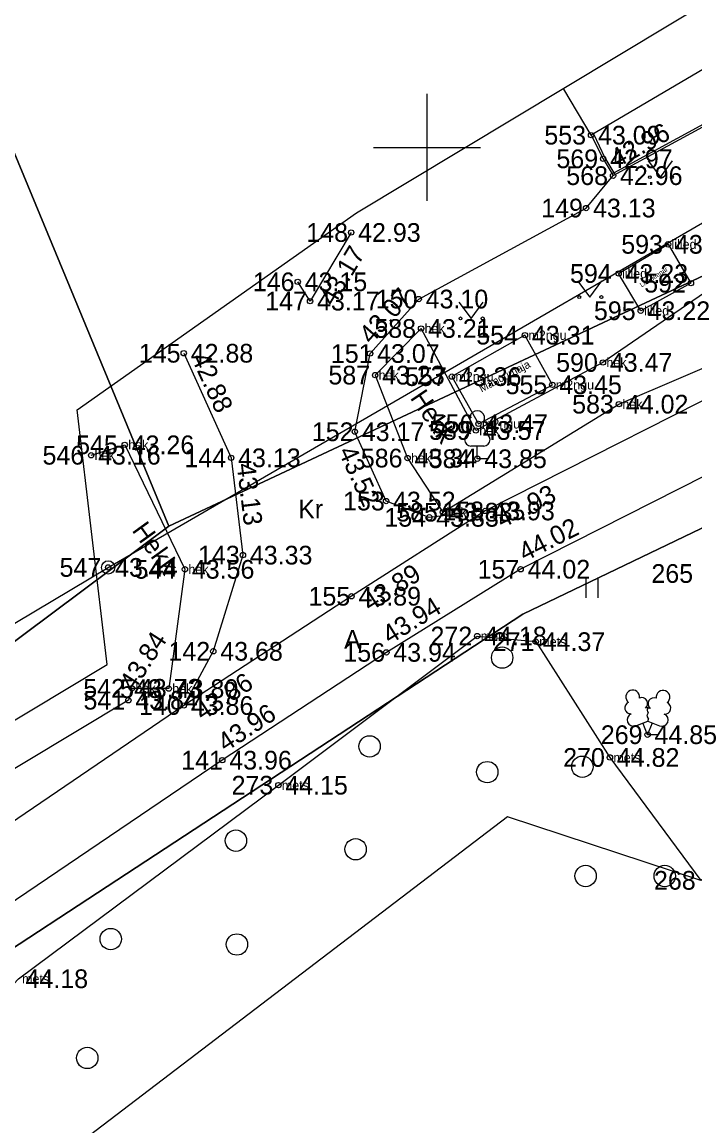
# Model space of a CAD drawing. Extents: x 505800 to 507326, y 6540058 to 6542128.
# Drawn here: x 506334.84 to 506360.03, y 6540313.38 to 6540354.69 of the extents above; entities that cross this region are included whole.
import ezdxf

# ---------------------------------------------------------------- set-up
doc = ezdxf.new("R2010")
doc.units = 0
for name, color, linetype in [('AED', 7, 'Continuous'), ('HALJASTUS', 7, 'Continuous'), ('HOONE', 7, 'Continuous'), ('KORGUS-EH2000', 7, 'Continuous'), ('MAAMUDEL', 7, 'Continuous'), ('MOOTKORG-EH2000', 7, 'Continuous'), ('MOOTMPUNKT', 7, 'Continuous'), ('MOOTNR', 7, 'Continuous'), ('MOOTPIIR', 7, 'Continuous'), ('MPOHULIIN', 7, 'Continuous'), ('PIIR', 7, 'Continuous'), ('POST', 7, 'Continuous'), ('PUU', 7, 'Continuous'), ('TEE', 7, 'Continuous'), ('VORK', 7, 'Continuous')]:
    doc.layers.add(name, color=color, linetype=linetype)

msp = doc.modelspace()

# ---------------------------------------------------------------- linework, layer by layer
at = {"layer": 'AED'}
msp.add_lwpolyline([(506338.82, 6540329.309), (506330.987, 6540324.61), (506320.117, 6540318.11)], dxfattribs=at)
at = {"layer": 'HALJASTUS'}
for p, q in [((506358.279, 6540349.492), (506358.742, 6540348.886)), ((506358.742, 6540348.886), (506359.188, 6540349.492)), ((506355.636, 6540345.005), (506356.1, 6540344.399)), ((506356.1, 6540344.399), (506356.545, 6540345.005)), ((506351.192, 6540344.204), (506351.656, 6540343.598)), ((506351.656, 6540343.598), (506352.101, 6540344.204)), ((506355.943, 6540333.904), (506355.943, 6540333.143)), ((506356.398, 6540333.904), (506356.398, 6540333.143))]:
    msp.add_line(p, q, dxfattribs=at)
for points in [[(506366.11, 6540347.866), (506361.968, 6540345.638), (506356.585, 6540341.95), (506351.827, 6540339.404), (506349.779, 6540343.223), (506348.059, 6540341.477), (506349.272, 6540338.372), (506350.597, 6540336.346), (506357.184, 6540340.389), (506361.938, 6540342.428), (506367.253, 6540345.293), (506366.11, 6540347.866)], [(506359.881, 6540344.919), (506357.999, 6540343.887), (506357.173, 6540345.28), (506359.023, 6540346.372), (506359.881, 6540344.919)], [(506337.427, 6540338.478), (506338.685, 6540338.868), (506340.937, 6540334.208), (506340.332, 6540329.743), (506338.953, 6540329.754), (506338.82, 6540329.309)], [(506306.227, 6540291.97), (506307.537, 6540296.92), (506309.208, 6540301.088), (506313.28, 6540303.838), (506321.716, 6540309.454), (506329.329, 6540313.144), (506334.711, 6540318.885), (506344.435, 6540326.129), (506351.88, 6540331.712), (506354.071, 6540331.501), (506356.847, 6540327.167), (506360.247, 6540322.568)]]:
    msp.add_lwpolyline(points, dxfattribs=at)
for centre, radius in [((506358.341, 6540348.886), 0.055), ((506359.17, 6540348.886), 0.055), ((506355.699, 6540344.399), 0.055), ((506356.527, 6540344.399), 0.055), ((506351.254, 6540343.598), 0.055), ((506352.083, 6540343.598), 0.055), ((506352.814, 6540330.904), 0.4), ((506347.85, 6540327.579), 0.4), ((506355.817, 6540326.818), 0.4), ((506352.254, 6540326.617), 0.4), ((506342.845, 6540324.053), 0.4), ((506347.329, 6540323.733), 0.4), ((506355.937, 6540322.731), 0.4), ((506358.9, 6540322.731), 0.4), ((506338.161, 6540320.368), 0.4), ((506342.885, 6540320.167), 0.4), ((506337.28, 6540315.921), 0.4)]:
    msp.add_circle(centre, radius, dxfattribs=at)
at = {"layer": 'HOONE'}
for p, q in [((506362.205, 6540354.024), (506356.142, 6540350.457)), ((506356.142, 6540350.457), (506355.128, 6540352.181))]:
    msp.add_line(p, q, dxfattribs=at)
msp.add_lwpolyline([(506350.932, 6540341.421), (506351.927, 6540339.655), (506354.692, 6540341.114), (506353.665, 6540342.972), (506350.932, 6540341.421)], dxfattribs=at)
at = {"layer": 'KORGUS-EH2000'}
for centre in [(506356.142, 6540350.457), (506356.594, 6540349.573), (506356.964, 6540348.942), (506355.956, 6540347.73), (506347.161, 6540346.815), (506359.023, 6540346.372), (506357.173, 6540345.28), (506345.16, 6540344.968), (506359.881, 6540344.919), (506345.623, 6540344.246), (506349.689, 6540344.324), (506357.999, 6540343.887), (506349.779, 6540343.223), (506353.665, 6540342.972), (506340.893, 6540342.297), (506347.871, 6540342.285), (506356.585, 6540341.95), (506348.059, 6540341.477), (506350.932, 6540341.421), (506354.692, 6540341.114), (506357.184, 6540340.389), (506351.827, 6540339.404), (506351.927, 6540339.655), (506347.299, 6540339.357), (506338.685, 6540338.868), (506337.427, 6540338.478), (506342.668, 6540338.381), (506349.272, 6540338.372), (506351.884, 6540338.347), (506348.468, 6540336.763), (506350.086, 6540336.154), (506350.597, 6540336.346), (506352.182, 6540336.393), (506343.108, 6540334.74), (506338.064, 6540334.279), (506340.937, 6540334.208), (506353.506, 6540334.212), (506347.174, 6540333.201), (506351.88, 6540331.712), (506342.001, 6540331.14), (506354.071, 6540331.501), (506348.479, 6540331.101), (506338.953, 6540329.754), (506340.332, 6540329.743), (506338.82, 6540329.309), (506340.898, 6540329.111), (506358.257, 6540328.019), (506342.338, 6540327.065), (506356.847, 6540327.167), (506344.435, 6540326.129)]:
    msp.add_circle(centre, 0.1, dxfattribs=at)
at = {"layer": 'MOOTMPUNKT'}
for centre in [(506356.142, 6540350.457), (506356.594, 6540349.573), (506356.964, 6540348.942), (506355.956, 6540347.73), (506347.161, 6540346.815), (506359.023, 6540346.372), (506357.173, 6540345.28), (506345.16, 6540344.968), (506359.881, 6540344.919), (506345.623, 6540344.246), (506349.689, 6540344.324), (506357.999, 6540343.887), (506349.779, 6540343.223), (506353.665, 6540342.972), (506340.893, 6540342.297), (506347.871, 6540342.285), (506356.585, 6540341.95), (506348.059, 6540341.477), (506350.932, 6540341.421), (506354.692, 6540341.114), (506357.184, 6540340.389), (506351.827, 6540339.404), (506351.927, 6540339.655), (506347.299, 6540339.357), (506338.685, 6540338.868), (506337.427, 6540338.478), (506342.668, 6540338.381), (506349.272, 6540338.372), (506351.884, 6540338.347), (506348.468, 6540336.763), (506350.086, 6540336.154), (506350.597, 6540336.346), (506352.182, 6540336.393), (506343.108, 6540334.74), (506338.064, 6540334.279), (506340.937, 6540334.208), (506353.506, 6540334.212), (506347.174, 6540333.201), (506351.88, 6540331.712), (506342.001, 6540331.14), (506354.071, 6540331.501), (506348.479, 6540331.101), (506338.953, 6540329.754), (506340.332, 6540329.743), (506338.82, 6540329.309), (506340.898, 6540329.111), (506358.257, 6540328.019), (506342.338, 6540327.065), (506356.847, 6540327.167), (506344.435, 6540326.129)]:
    msp.add_circle(centre, 0.1, dxfattribs=at)
at = {"layer": 'MOOTPIIR'}
for points in [[(506240.253, 6540270.959), (506245.955, 6540263.864), (506266.133, 6540270.794), (506275.983, 6540276.683), (506285.511, 6540285.657), (506298.843, 6540299.878), (506301.086, 6540304.525), (506297.722, 6540312.738), (506305.023, 6540318.445), (506309.38, 6540311.746), (506312.325, 6540315.185), (506338.029, 6540330.648), (506336.908, 6540340.183), (506347.357, 6540347.554), (506370.89, 6540361.705), (506382.389, 6540366.462), (506390.076, 6540368.866), (506400.572, 6540374.13), (506410.565, 6540381.71), (506441.143, 6540393.151), (506453.59, 6540403.335), (506461.402, 6540393.473), (506495.448, 6540402.285)], [(506495.183, 6540386.603), (506455.807, 6540378.751), (506413.936, 6540356.957), (506411.426, 6540354.112), (506402.307, 6540351.523), (506391.999, 6540341.498), (506380.901, 6540334.942), (506360.247, 6540322.568), (506353.013, 6540324.95), (506332.133, 6540309.036), (506315.598, 6540297.889), (506301.375, 6540281.904), (506292.827, 6540267.673), (506286.653, 6540264.508), (506248.469, 6540250.071)]]:
    msp.add_lwpolyline(points, dxfattribs=at)
at = {"layer": 'MPOHULIIN'}
msp.add_line((506305.802, 6540315.044), (506338.064, 6540334.279), dxfattribs=at)
msp.add_lwpolyline([(506338.064, 6540334.279), (506372.493, 6540354.233), (506366.077, 6540356.302)], dxfattribs=at)
at = {"layer": 'PIIR'}
for points in [[(506326.14, 6540370.11), (506324.04, 6540375.18), (506354.05, 6540393.57), (506395.54, 6540418.74), (506427.6, 6540438.79), (506429.21, 6540436.36), (506458.7, 6540391.28), (506340.34, 6540335.82)], [(506281.36, 6540349.61), (506321.08, 6540373.36), (506324.04, 6540375.18), (506326.14, 6540370.11), (506340.34, 6540335.82), (506304.35, 6540308.95), (506282.62, 6540347.28)]]:
    msp.add_lwpolyline(points, close=True, dxfattribs=at)
for points in [[(506215.95, 6540254.34), (506268.55, 6540273.9), (506274.54, 6540277.85), (506304.35, 6540308.95), (506340.34, 6540335.82), (506458.7, 6540391.28), (506563.96, 6540420.02)], [(506497.85, 6540391.32), (506462.8, 6540384.69), (506453.27, 6540382.76), (506413.82, 6540364.84), (506374.55, 6540342.6), (506353.59, 6540332.53), (506318.07, 6540309.28), (506308, 6540301.95), (506281.65, 6540275.05), (506272.39, 6540267.75), (506224.13, 6540249.92)], [(506224.13, 6540249.92), (506272.39, 6540267.75), (506281.65, 6540275.05), (506308, 6540301.95), (506318.07, 6540309.28), (506353.59, 6540332.53), (506374.55, 6540342.6), (506413.82, 6540364.84), (506453.27, 6540382.76), (506462.8, 6540384.69), (506495.14, 6540337.45), (506342.85, 6540237.27), (506260.72, 6540195.9), (506215.68, 6540179.69)]]:
    msp.add_lwpolyline(points, dxfattribs=at)
at = {"layer": 'POST'}
msp.add_circle((506338.064, 6540334.279), 0.25, dxfattribs=at)
at = {"layer": 'PUU'}
for p, q in [((506352.124, 6540338.822), (506351.644, 6540338.822)), ((506351.884, 6540338.347), (506351.884, 6540338.822)), ((506352.264, 6540338.347), (506351.884, 6540338.347)), ((506357.817, 6540328.354), (506358.262, 6540328.529)), ((506358.257, 6540328.019), (506358.082, 6540328.459)), ((506358.257, 6540328.019), (506358.437, 6540328.459)), ((506358.262, 6540328.529), (506358.702, 6540328.349)), ((506358.637, 6540328.019), (506358.257, 6540328.019))]:
    msp.add_line(p, q, dxfattribs=at)
msp.add_lwpolyline([(506358.262, 6540329.024), (506358.242, 6540328.949), (506358.242, 6540328.929), (506358.252, 6540328.899), (506358.272, 6540328.864), (506358.277, 6540328.844), (506358.262, 6540328.809), (506358.237, 6540328.759), (506358.232, 6540328.734), (506358.237, 6540328.719), (506358.247, 6540328.689), (506358.282, 6540328.629), (506358.287, 6540328.609), (506358.282, 6540328.589), (506358.267, 6540328.554), (506358.262, 6540328.529)], dxfattribs=at)
for centre, radius, start, end in [((506351.884, 6540339.867), 0.277, 332.5799, 207.4201), ((506351.714, 6540339.52), 0.233, 109.0217, 253.1415), ((506352.055, 6540339.52), 0.233, 286.8508, 70.9859), ((506351.647, 6540339.06), 0.238, 90.0016, 269.3953), ((506352.122, 6540339.06), 0.238, 270.6047, 89.9984), ((506357.7, 6540329.433), 0.256, 111.5027, 232.5173), ((506357.7, 6540329.433), 0.256, 350.4856, 111.5002), ((506358.836, 6540329.424), 0.256, 67.6168, 188.6314), ((506358.836, 6540329.424), 0.256, 306.5997, 67.6143), ((506357.626, 6540329.022), 0.224, 111.4304, 274.4987), ((506358.035, 6540329.183), 0.224, 308.5041, 111.5725), ((506358.498, 6540329.178), 0.225, 67.7016, 230.5126), ((506358.904, 6540329.012), 0.224, 264.6183, 67.6866), ((506357.731, 6540328.577), 0.237, 111.5014, 291.5004), ((506358.261, 6540328.786), 0.237, 66.7655, 111.5015), ((506358.792, 6540328.569), 0.237, 247.6166, 67.6155)]:
    msp.add_arc(centre, radius, start, end, dxfattribs=at)
at = {"layer": 'TEE'}
for points in [[(506478.706, 6540392.058), (506464.091, 6540389.4), (506454.678, 6540387.173), (506446.264, 6540384.451), (506435.18, 6540379.372), (506420.092, 6540372.182), (506407.957, 6540366.228), (506394.897, 6540359.329), (506383.759, 6540352.819), (506372.647, 6540346.37), (506363.224, 6540341.99), (506352.182, 6540336.393), (506347.174, 6540333.201), (506340.898, 6540329.111), (506329.323, 6540321.237)], [(506479.167, 6540389.797), (506464.651, 6540387.028), (506455.166, 6540384.708), (506447.071, 6540382.035), (506436.402, 6540377.232), (506421.232, 6540370.083), (506409.03, 6540364.194), (506396.144, 6540357.137), (506385.127, 6540350.766), (506373.749, 6540344.271), (506364.374, 6540339.718), (506353.506, 6540334.212), (506348.479, 6540331.101), (506342.338, 6540327.065), (506330.786, 6540319.25)], [(506356.142, 6540350.457), (506356.594, 6540349.573), (506356.964, 6540348.942), (506363.98, 6540352.757), (506365.964, 6540349.197), (506367.02, 6540347.089), (506367.201, 6540346.736)], [(506356.229, 6540350.506), (506356.663, 6540349.613), (506356.993, 6540349.049), (506364.011, 6540352.865), (506366.034, 6540349.235), (506367.092, 6540347.125), (506367.268, 6540346.769)], [(506352.182, 6540336.393), (506350.086, 6540336.154), (506348.468, 6540336.763), (506347.299, 6540339.357), (506347.871, 6540342.285), (506349.689, 6540344.324), (506355.956, 6540347.73), (506356.964, 6540348.942)], [(506347.161, 6540346.815), (506345.623, 6540344.246), (506345.16, 6540344.968)], [(506340.893, 6540342.297), (506342.668, 6540338.381), (506343.108, 6540334.74), (506342.001, 6540331.14), (506340.898, 6540329.111)]]:
    msp.add_lwpolyline(points, dxfattribs=at)
at = {"layer": 'VORK'}
for p, q in [((506350, 6540352), (506350, 6540348)), ((506348, 6540350), (506352, 6540350))]:
    msp.add_line(p, q, dxfattribs=at)

# ---------------------------------------------------------------- texts
at = {"layer": 'HALJASTUS'}
for s, height, rotation, p in [('Lillepeenar', 0.175, 32.5305, (506358.037, 6540344.758)), ('Hekk', 0.7, 304.0004, (506349.346, 6540340.626)), ('Hekk', 0.7, 305.7666, (506338.931, 6540335.666))]:
    msp.add_text(s, height=height, rotation=rotation, dxfattribs=at).set_placement(p)
at = {"layer": 'HOONE'}
msp.add_text('Mängumaja', height=0.3, rotation=27.3359, dxfattribs=at).set_placement((506352.039, 6540340.823))
at = {"layer": 'KORGUS-EH2000'}
for s, rotation, p in [(' 42.96', 28.531, (506356.88, 6540349.096)), (' 43.17', 59.0996, (506346.374, 6540343.797)), (' 43.07', 48.2861, (506347.741, 6540342.402)), (' 42.88', 294.3865, (506341.052, 6540342.369)), (' 43.52', 294.2571, (506346.562, 6540338.864)), (' 43.13', 276.8945, (506342.842, 6540338.402)), (' 43.93', 26.8815, (506352.577, 6540335.612)), (' 44.02', 26.8698, (506353.427, 6540334.368)), (' 43.89', 32.5095, (506347.644, 6540332.464)), (' 43.94', 31.7518, (506348.387, 6540331.25)), (' 43.84', 57.1855, (506338.884, 6540329.39)), (' 43.86', 33.0902, (506341.375, 6540328.378)), (' 43.96', 33.3119, (506342.242, 6540327.211))]:
    msp.add_text(s, height=0.7, rotation=rotation, dxfattribs=at).set_placement(p)
for s, p in [(' 43.18', (506359.023, 6540346.022)), (' 43.31', (506353.665, 6540342.622)), (' 44.02', (506357.184, 6540340.039)), (' 43.26', (506338.685, 6540338.518)), (' 44.37', (506354.071, 6540331.151)), (' 44.82', (506356.847, 6540326.817)), (' 44.15', (506344.435, 6540325.779)), (' 44.18', (506334.711, 6540318.535))]:
    msp.add_text(s, height=0.7, dxfattribs=at).set_placement(p)
at = {"layer": 'MAAMUDEL'}
for s, p in [(' lilled', (506359.023, 6540346.197)), (' lilled', (506357.173, 6540345.105)), (' lilled', (506357.999, 6540343.712)), (' hek', (506349.779, 6540343.048)), (' m2ngu', (506353.665, 6540342.797)), (' hek', (506356.585, 6540341.775)), (' hek', (506348.059, 6540341.302)), (' m2ngu', (506350.932, 6540341.246)), (' m2ngu', (506354.692, 6540340.939)), (' hek', (506357.184, 6540340.214)), (' hek', (506351.827, 6540339.229)), (' m2ngu', (506351.927, 6540339.48)), (' hek', (506337.427, 6540338.303)), (' hek', (506338.685, 6540338.693)), (' hek', (506349.272, 6540338.197)), (' hek', (506350.597, 6540336.171)), (' hek', (506340.937, 6540334.033)), (' mets', (506351.88, 6540331.536)), (' mets', (506354.071, 6540331.326)), (' hek', (506338.953, 6540329.579)), (' hek', (506340.332, 6540329.568)), (' mets', (506356.847, 6540326.992)), (' mets', (506344.435, 6540325.954)), (' mets', (506334.711, 6540318.71))]:
    msp.add_text(s, height=0.35, dxfattribs=at).set_placement(p)
at = {"layer": 'MOOTKORG-EH2000'}
for s, p in [(' 43.09', (506356.142, 6540350.107)), (' 42.97', (506356.594, 6540349.223)), (' 42.96', (506356.964, 6540348.592)), (' 43.13', (506355.956, 6540347.38)), (' 42.93', (506347.161, 6540346.465)), (' 43.18', (506359.023, 6540346.022)), (' 43.15', (506345.16, 6540344.618)), (' 43.23', (506357.173, 6540344.93)), (' 43.17', (506345.623, 6540343.896)), (' 43.10', (506349.689, 6540343.974)), (' 43.22', (506357.999, 6540343.537)), (' 43.21', (506349.779, 6540342.873)), (' 43.31', (506353.665, 6540342.622)), (' 42.88', (506340.893, 6540341.946)), (' 43.07', (506347.871, 6540341.935)), (' 43.47', (506356.585, 6540341.6)), (' 43.23', (506348.059, 6540341.127)), (' 43.36', (506350.932, 6540341.071)), (' 43.45', (506354.692, 6540340.764)), (' 44.02', (506357.184, 6540340.039)), (' 43.47', (506351.927, 6540339.305)), (' 43.17', (506347.299, 6540339.007)), (' 43.57', (506351.827, 6540339.054)), (' 43.26', (506338.685, 6540338.518)), (' 43.16', (506337.427, 6540338.128)), (' 43.13', (506342.668, 6540338.031)), (' 43.34', (506349.272, 6540338.022)), (' 43.85', (506351.884, 6540337.997)), (' 43.52', (506348.468, 6540336.413)), (' 43.83', (506350.597, 6540335.996)), (' 43.93', (506352.182, 6540336.043)), (' 43.83', (506350.086, 6540335.804)), (' 43.33', (506343.108, 6540334.39)), (' 43.44', (506338.064, 6540333.929)), (' 43.56', (506340.937, 6540333.858)), (' 44.02', (506353.506, 6540333.862)), (' 43.89', (506347.174, 6540332.851)), (' 44.18', (506351.88, 6540331.361)), (' 44.37', (506354.071, 6540331.151)), (' 43.68', (506342.001, 6540330.79)), (' 43.94', (506348.479, 6540330.751)), (' 43.73', (506338.953, 6540329.404)), (' 43.80', (506340.332, 6540329.393)), (' 43.84', (506338.82, 6540328.959)), (' 43.86', (506340.898, 6540328.761)), (' 44.85', (506358.257, 6540327.669)), (' 44.82', (506356.847, 6540326.817)), (' 43.96', (506342.338, 6540326.715)), (' 44.15', (506344.435, 6540325.779)), (' 44.18', (506334.711, 6540318.535))]:
    msp.add_text(s, height=0.7, dxfattribs=at).set_placement(p)
at = {"layer": 'MOOTNR'}
for s, p in [('553 ', (506354.392, 6540350.107)), ('569 ', (506354.844, 6540349.223)), ('568 ', (506355.214, 6540348.592)), ('149 ', (506354.276, 6540347.38)), ('148 ', (506345.481, 6540346.465)), ('593 ', (506357.273, 6540346.022)), ('146 ', (506343.48, 6540344.618)), ('594 ', (506355.353, 6540344.93)), ('592 ', (506358.131, 6540344.569)), ('147 ', (506343.943, 6540343.896)), ('150 ', (506348.079, 6540343.974)), ('595 ', (506356.249, 6540343.537)), ('588 ', (506348.029, 6540342.873)), ('554 ', (506351.845, 6540342.622)), ('145 ', (506339.213, 6540341.946)), ('151 ', (506346.401, 6540341.935)), ('590 ', (506354.835, 6540341.6)), ('587 ', (506346.309, 6540341.127)), ('557 ', (506349.182, 6540341.071)), ('555 ', (506352.942, 6540340.764)), ('583 ', (506355.434, 6540340.039)), ('556 ', (506350.177, 6540339.305)), ('152 ', (506345.689, 6540339.007)), ('589 ', (506350.077, 6540339.054)), ('545 ', (506336.865, 6540338.518)), ('546 ', (506335.607, 6540338.128)), ('144 ', (506340.918, 6540338.031)), ('586 ', (506347.522, 6540338.022)), ('584 ', (506350.065, 6540337.997)), ('153 ', (506346.858, 6540336.413)), ('585 ', (506348.847, 6540335.996)), ('158 ', (506350.572, 6540336.043)), ('154 ', (506348.406, 6540335.804)), ('143 ', (506341.428, 6540334.39)), ('547 ', (506336.244, 6540333.929)), ('544 ', (506339.047, 6540333.858)), ('157 ', (506351.896, 6540333.862)), ('265 ', (506358.401, 6540333.702)), ('155 ', (506345.564, 6540332.851)), ('272 ', (506350.13, 6540331.361)), ('271 ', (506352.461, 6540331.151)), ('142 ', (506340.321, 6540330.79)), ('156 ', (506346.869, 6540330.751)), ('542 ', (506337.133, 6540329.404)), ('543 ', (506338.512, 6540329.393)), ('541 ', (506337.14, 6540328.959)), ('140 ', (506339.218, 6540328.761)), ('269 ', (506356.507, 6540327.669)), ('270 ', (506355.097, 6540326.817)), ('141 ', (506340.798, 6540326.715)), ('273 ', (506342.685, 6540325.779)), ('268 ', (506358.497, 6540322.218))]:
    msp.add_text(s, height=0.7, dxfattribs=at).set_placement(p)
at = {"layer": 'TEE'}
for s, p in [('Kr', (506345.176, 6540336.114)), ('A', (506346.897, 6540331.236))]:
    msp.add_text(s, height=0.7, dxfattribs=at).set_placement(p)

doc.saveas('drawing.dxf')
